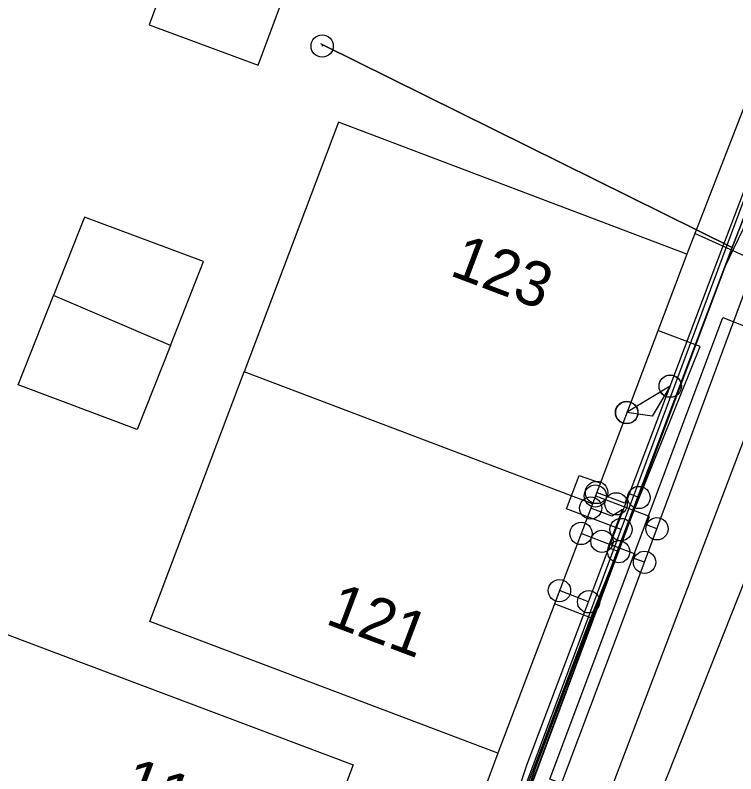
# Model space of a CAD drawing. Extents: x 192672 to 192910, y 446344 to 446512.
# Drawn here: x 192711.22 to 192727.4, y 446363.89 to 446380.91 of the extents above; entities that cross this region are included whole.
import ezdxf

# ---------------------------------------------------------------- set-up
doc = ezdxf.new("R2010")
doc.units = 0
for name, color, linetype in [('B-OI-KL-()_PUNTVANLEVERING_WATER-S', 7, 'Continuous'), ('B-OI-KL-BUISLEIDING_OLIEGASCHEMICALIEN_GASLAGEDRUK-G', 7, 'Continuous'), ('B-OI-KL-DATA-G', 7, 'Continuous'), ('B-OI-KL-DATA_GTWP-S', 7, 'Continuous'), ('B-OI-KL-DATA_HULPSTUK-S', 7, 'Continuous'), ('B-OI-KL-DATA_KABELBED-G', 7, 'Continuous'), ('B-OI-KL-DATA_MOF-S', 7, 'Continuous'), ('B-OI-KL-ET_LS-G', 7, 'Continuous'), ('B-OI-KL-ET_LS_DELIVERYPOINT-S', 7, 'Continuous'), ('B-OI-KL-ET_LS_MOF-S', 7, 'Continuous'), ('B-OI-KL-GAS_LD_AFTAKZADEL-S', 7, 'Continuous'), ('B-OI-KL-GAS_LD_DELIVERYPOINT-S', 7, 'Continuous'), ('B-OI-KL-GAS_LD_OVERGANGSSTUK-S', 7, 'Continuous'), ('B-OI-KL-WATER-G', 7, 'Continuous'), ('B-OI-RI-RIOOLVRIJVERVAL-G', 7, 'Continuous'), ('Default', 7, 'Continuous'), ('grens niveau plus 1', 7, 'Continuous'), ('huisnummerreeks BGT', 7, 'Continuous'), ('kant open verharding', 7, 'Continuous'), ('kant verharding', 7, 'Continuous'), ('pand op maaiveld vlak', 7, 'Continuous')]:
    doc.layers.add(name, color=color, linetype=linetype)

# ---------------------------------------------------------------- blocks, each defined once
blk = doc.blocks.new('B-OI-KL-DATA_HULPSTUK-S')
at = {"layer": 'Default'}
blk.add_circle((0, 0), 0.25, dxfattribs=at)
blk = doc.blocks.new('B-OI-KL-GAS_LD_AFTAKZADEL-S')
at = {"layer": 'Default'}
blk.add_circle((0, 0), 0.25, dxfattribs=at)
blk = doc.blocks.new('B-OI-KL-GAS_LD_DELIVERYPOINT-S')
at = {"layer": 'Default'}
blk.add_circle((0, 0), 0.25, dxfattribs=at)
blk = doc.blocks.new('B-OI-KL-GAS_LD_OVERGANGSSTUK-S')
at = {"layer": 'Default'}
blk.add_circle((0, 0), 0.25, dxfattribs=at)
blk = doc.blocks.new('B-OI-KL-ET_LS_DELIVERYPOINT-S')
at = {"layer": 'Default'}
blk.add_circle((0, 0), 0.25, dxfattribs=at)
blk = doc.blocks.new('B-OI-KL-ET_LS_MOF-S')
at = {"layer": 'Default'}
blk.add_circle((0, 0), 0.25, dxfattribs=at)
blk = doc.blocks.new('B-OI-KL-()_PUNTVANLEVERING_WATER-S')
at = {"layer": 'Default'}
blk.add_circle((0, 0), 0.25, dxfattribs=at)
blk = doc.blocks.new('B-OI-KL-DATA_GTWP-S')
at = {"layer": 'Default'}
blk.add_circle((0, 0), 0.25, dxfattribs=at)
blk = doc.blocks.new('B-OI-KL-DATA_MOF-S')
at = {"layer": 'Default'}
blk.add_circle((0, 0), 0.25, dxfattribs=at)

msp = doc.modelspace()

# ---------------------------------------------------------------- linework, layer by layer
at = {"layer": 'B-OI-KL-BUISLEIDING_OLIEGASCHEMICALIEN_GASLAGEDRUK-G'}
for points in [[(192716.663, 446345.556), (192724.878, 446367.369), (192730.944, 446383.739), (192732.424, 446387.662), (192733.825, 446391.479)], [(192724.71, 446369.947), (192724.242, 446370.124)], [(192725.626, 446369.387), (192725.391, 446369.473), (192725.461, 446369.662), (192724.71, 446369.947)], [(192724.391, 446369.105), (192723.923, 446369.282)], [(192725.348, 446368.636), (192725.113, 446368.723), (192725.148, 446368.818), (192724.391, 446369.105)]]:
    msp.add_lwpolyline(points, dxfattribs=at)
at = {"layer": 'B-OI-KL-DATA-G'}
for points in [[(192768.74, 446486.807), (192749.794, 446435.599), (192742.072, 446415.039), (192739.06, 446406.841), (192738.917, 446406.249), (192738.75, 446405.758), (192738.438, 446405.088), (192738.002, 446404.406), (192737.543, 446403.858), (192737.067, 446403.408), (192736.56, 446403.025), (192736.06, 446402.723), (192733.684, 446396.245), (192734.518, 446394.712), (192730.316, 446383.423), (192727.316, 446375.697), (192722.899, 446364.033), (192722.458, 446362.715), (192718.077, 446351.086), (192716.68, 446347.404), (192715.968, 446345.556)], [(192768.74, 446486.807), (192749.794, 446435.599), (192742.072, 446415.039), (192739.06, 446406.841), (192738.917, 446406.249), (192738.75, 446405.758), (192738.438, 446405.088), (192738.002, 446404.406), (192737.543, 446403.858), (192737.067, 446403.408), (192736.56, 446403.025), (192736.06, 446402.723), (192733.684, 446396.245), (192734.518, 446394.712), (192730.316, 446383.423), (192727.316, 446375.697), (192722.899, 446364.033), (192722.458, 446362.715), (192718.077, 446351.086), (192716.68, 446347.404), (192715.968, 446345.556)], [(192768.74, 446486.807), (192749.794, 446435.599), (192742.072, 446415.039), (192739.06, 446406.841), (192738.917, 446406.249), (192738.75, 446405.758), (192738.438, 446405.088), (192738.002, 446404.406), (192737.543, 446403.858), (192737.067, 446403.408), (192736.56, 446403.025), (192736.06, 446402.723), (192733.684, 446396.245), (192734.518, 446394.712), (192730.316, 446383.423), (192727.316, 446375.697), (192722.899, 446364.033), (192722.458, 446362.715), (192718.077, 446351.086), (192716.68, 446347.404), (192715.968, 446345.556)], [(192768.74, 446486.807), (192749.794, 446435.599), (192742.072, 446415.039), (192739.06, 446406.841), (192738.917, 446406.249), (192738.75, 446405.758), (192738.438, 446405.088), (192738.002, 446404.406), (192737.543, 446403.858), (192737.067, 446403.408), (192736.56, 446403.025), (192736.06, 446402.723), (192733.684, 446396.245), (192734.518, 446394.712), (192730.316, 446383.423), (192727.316, 446375.697), (192722.899, 446364.033), (192722.458, 446362.715), (192718.077, 446351.086), (192716.68, 446347.404), (192715.968, 446345.556)], [(192768.74, 446486.807), (192749.794, 446435.599), (192742.072, 446415.039), (192739.06, 446406.841), (192738.917, 446406.249), (192738.75, 446405.758), (192738.438, 446405.088), (192738.002, 446404.406), (192737.543, 446403.858), (192737.067, 446403.408), (192736.56, 446403.025), (192736.06, 446402.723), (192733.684, 446396.245), (192734.518, 446394.712), (192730.316, 446383.423), (192727.316, 446375.697), (192722.899, 446364.033), (192722.458, 446362.715), (192718.077, 446351.086), (192716.68, 446347.404), (192715.968, 446345.556)], [(192768.74, 446486.807), (192749.794, 446435.599), (192742.072, 446415.039), (192739.06, 446406.841), (192738.917, 446406.249), (192738.75, 446405.758), (192738.438, 446405.088), (192738.002, 446404.406), (192737.543, 446403.858), (192737.067, 446403.408), (192736.56, 446403.025), (192736.06, 446402.723), (192733.684, 446396.245), (192734.518, 446394.712), (192730.316, 446383.423), (192727.316, 446375.697), (192722.899, 446364.033), (192722.458, 446362.715), (192718.077, 446351.086), (192716.68, 446347.404), (192715.968, 446345.556)], [(192768.74, 446486.807), (192749.794, 446435.599), (192742.072, 446415.039), (192739.06, 446406.841), (192738.917, 446406.249), (192738.75, 446405.758), (192738.438, 446405.088), (192738.002, 446404.406), (192737.543, 446403.858), (192737.067, 446403.408), (192736.56, 446403.025), (192736.06, 446402.723), (192733.684, 446396.245), (192734.518, 446394.712), (192730.316, 446383.423), (192727.316, 446375.697), (192722.899, 446364.033), (192722.458, 446362.715), (192718.077, 446351.086), (192716.68, 446347.404), (192715.968, 446345.556)], [(192768.74, 446486.807), (192749.794, 446435.599), (192742.072, 446415.039), (192739.06, 446406.841), (192738.917, 446406.249), (192738.75, 446405.758), (192738.438, 446405.088), (192738.002, 446404.406), (192737.543, 446403.858), (192737.067, 446403.408), (192736.56, 446403.025), (192736.06, 446402.723), (192733.684, 446396.245), (192734.518, 446394.712), (192730.316, 446383.423), (192727.316, 446375.697), (192722.899, 446364.033), (192722.458, 446362.715), (192718.077, 446351.086), (192716.68, 446347.404), (192715.968, 446345.556)], [(192768.74, 446486.807), (192749.794, 446435.599), (192742.072, 446415.039), (192739.06, 446406.841), (192738.917, 446406.249), (192738.75, 446405.758), (192738.438, 446405.088), (192738.002, 446404.406), (192737.543, 446403.858), (192737.067, 446403.408), (192736.56, 446403.025), (192736.06, 446402.723), (192733.684, 446396.245), (192734.518, 446394.712), (192730.316, 446383.423), (192727.316, 446375.697), (192722.899, 446364.033), (192722.458, 446362.715), (192718.077, 446351.086), (192716.68, 446347.404), (192715.968, 446345.556)], [(192768.74, 446486.807), (192749.794, 446435.599), (192742.072, 446415.039), (192739.06, 446406.841), (192738.917, 446406.249), (192738.75, 446405.758), (192738.438, 446405.088), (192738.002, 446404.406), (192737.543, 446403.858), (192737.067, 446403.408), (192736.56, 446403.025), (192736.06, 446402.723), (192733.684, 446396.245), (192734.518, 446394.712), (192730.316, 446383.423), (192727.316, 446375.697), (192722.899, 446364.033), (192722.458, 446362.715), (192718.077, 446351.086), (192716.68, 446347.404), (192715.968, 446345.556)], [(192768.74, 446486.807), (192749.794, 446435.599), (192742.072, 446415.039), (192739.06, 446406.841), (192738.917, 446406.249), (192738.75, 446405.758), (192738.438, 446405.088), (192738.002, 446404.406), (192737.543, 446403.858), (192737.067, 446403.408), (192736.56, 446403.025), (192736.06, 446402.723), (192733.684, 446396.245), (192734.518, 446394.712), (192730.316, 446383.423), (192727.316, 446375.697), (192722.899, 446364.033), (192722.458, 446362.715), (192718.077, 446351.086), (192716.68, 446347.404), (192715.968, 446345.556)], [(192768.74, 446486.807), (192749.794, 446435.599), (192742.072, 446415.039), (192739.06, 446406.841), (192738.917, 446406.249), (192738.75, 446405.758), (192738.438, 446405.088), (192738.002, 446404.406), (192737.543, 446403.858), (192737.067, 446403.408), (192736.56, 446403.025), (192736.06, 446402.723), (192733.684, 446396.245), (192734.518, 446394.712), (192730.316, 446383.423), (192727.316, 446375.697), (192722.899, 446364.033), (192722.458, 446362.715), (192718.077, 446351.086), (192716.68, 446347.404), (192715.968, 446345.556)], [(192768.74, 446486.807), (192749.794, 446435.599), (192742.072, 446415.039), (192739.06, 446406.841), (192738.917, 446406.249), (192738.75, 446405.758), (192738.438, 446405.088), (192738.002, 446404.406), (192737.543, 446403.858), (192737.067, 446403.408), (192736.56, 446403.025), (192736.06, 446402.723), (192733.684, 446396.245), (192734.518, 446394.712), (192730.316, 446383.423), (192727.316, 446375.697), (192722.899, 446364.033), (192722.458, 446362.715), (192718.077, 446351.086), (192716.68, 446347.404), (192715.968, 446345.556)], [(192768.74, 446486.807), (192749.794, 446435.599), (192742.072, 446415.039), (192739.06, 446406.841), (192738.917, 446406.249), (192738.75, 446405.758), (192738.438, 446405.088), (192738.002, 446404.406), (192737.543, 446403.858), (192737.067, 446403.408), (192736.56, 446403.025), (192736.06, 446402.723), (192733.684, 446396.245), (192734.518, 446394.712), (192730.316, 446383.423), (192727.316, 446375.697), (192722.899, 446364.033), (192722.458, 446362.715), (192718.077, 446351.086), (192716.68, 446347.404), (192715.968, 446345.556)], [(192768.74, 446486.807), (192749.794, 446435.599), (192742.072, 446415.039), (192739.06, 446406.841), (192738.917, 446406.249), (192738.75, 446405.758), (192738.438, 446405.088), (192738.002, 446404.406), (192737.543, 446403.858), (192737.067, 446403.408), (192736.56, 446403.025), (192736.06, 446402.723), (192733.684, 446396.245), (192734.518, 446394.712), (192730.316, 446383.423), (192727.316, 446375.697), (192722.899, 446364.033), (192722.458, 446362.715), (192718.077, 446351.086), (192716.68, 446347.404), (192715.968, 446345.556)], [(192675.743, 446430.156), (192678.122, 446429.261), (192683.193, 446427.673), (192696.077, 446422.823), (192719.012, 446414.118), (192720.2, 446413.77), (192739.06, 446406.841), (192738.917, 446406.249), (192738.75, 446405.758), (192738.438, 446405.088), (192738.002, 446404.406), (192737.543, 446403.858), (192737.067, 446403.408), (192736.56, 446403.025), (192736.06, 446402.723), (192733.684, 446396.245), (192734.518, 446394.712), (192730.316, 446383.423), (192727.316, 446375.697), (192722.899, 446364.033), (192722.458, 446362.715), (192718.077, 446351.086), (192716.68, 446347.404), (192715.968, 446345.556)], [(192675.743, 446430.156), (192678.122, 446429.261), (192683.193, 446427.673), (192696.077, 446422.823), (192719.012, 446414.118), (192720.2, 446413.77), (192739.06, 446406.841), (192738.917, 446406.249), (192738.75, 446405.758), (192738.438, 446405.088), (192738.002, 446404.406), (192737.543, 446403.858), (192737.067, 446403.408), (192736.56, 446403.025), (192736.06, 446402.723), (192733.684, 446396.245), (192734.518, 446394.712), (192730.316, 446383.423), (192727.316, 446375.697), (192722.899, 446364.033), (192722.458, 446362.715), (192718.077, 446351.086), (192716.68, 446347.404), (192715.968, 446345.556)], [(192675.743, 446430.156), (192678.122, 446429.261), (192683.193, 446427.673), (192696.077, 446422.823), (192719.012, 446414.118), (192720.2, 446413.77), (192739.06, 446406.841), (192738.917, 446406.249), (192738.75, 446405.758), (192738.438, 446405.088), (192738.002, 446404.406), (192737.543, 446403.858), (192737.067, 446403.408), (192736.56, 446403.025), (192736.06, 446402.723), (192733.684, 446396.245), (192734.518, 446394.712), (192730.316, 446383.423), (192727.316, 446375.697), (192722.899, 446364.033), (192722.458, 446362.715), (192718.077, 446351.086), (192716.68, 446347.404), (192715.968, 446345.556)], [(192675.743, 446430.156), (192678.122, 446429.261), (192683.193, 446427.673), (192696.077, 446422.823), (192719.012, 446414.118), (192720.2, 446413.77), (192739.06, 446406.841), (192738.917, 446406.249), (192738.75, 446405.758), (192738.438, 446405.088), (192738.002, 446404.406), (192737.543, 446403.858), (192737.067, 446403.408), (192736.56, 446403.025), (192736.06, 446402.723), (192733.684, 446396.245), (192734.518, 446394.712), (192730.316, 446383.423), (192727.316, 446375.697), (192722.899, 446364.033), (192722.458, 446362.715), (192718.077, 446351.086), (192716.68, 446347.404), (192715.968, 446345.556)], [(192675.743, 446430.156), (192678.122, 446429.261), (192683.193, 446427.673), (192696.077, 446422.823), (192719.012, 446414.118), (192720.2, 446413.77), (192739.06, 446406.841), (192738.917, 446406.249), (192738.75, 446405.758), (192738.438, 446405.088), (192738.002, 446404.406), (192737.543, 446403.858), (192737.067, 446403.408), (192736.56, 446403.025), (192736.06, 446402.723), (192733.684, 446396.245), (192734.518, 446394.712), (192730.316, 446383.423), (192727.316, 446375.697), (192722.899, 446364.033), (192722.458, 446362.715), (192718.077, 446351.086), (192716.68, 446347.404), (192715.968, 446345.556)], [(192675.743, 446430.156), (192678.122, 446429.261), (192683.193, 446427.673), (192696.077, 446422.823), (192719.012, 446414.118), (192720.2, 446413.77), (192739.06, 446406.841), (192738.917, 446406.249), (192738.75, 446405.758), (192738.438, 446405.088), (192738.002, 446404.406), (192737.543, 446403.858), (192737.067, 446403.408), (192736.56, 446403.025), (192736.06, 446402.723), (192733.684, 446396.245), (192734.518, 446394.712), (192730.316, 446383.423), (192727.316, 446375.697), (192722.899, 446364.033), (192722.458, 446362.715), (192718.077, 446351.086), (192716.68, 446347.404), (192715.968, 446345.556)], [(192715.968, 446345.556), (192716.68, 446347.404), (192718.077, 446351.086), (192722.458, 446362.715), (192722.899, 446364.033), (192727.316, 446375.697), (192730.316, 446383.423), (192734.518, 446394.712), (192733.684, 446396.245), (192736.06, 446402.723), (192736.56, 446403.025), (192737.067, 446403.408), (192737.543, 446403.858), (192738.002, 446404.406), (192738.438, 446405.088), (192738.75, 446405.758), (192738.917, 446406.249), (192739.06, 446406.841), (192720.2, 446413.77), (192719.012, 446414.118), (192698.154, 446422.035)], [(192715.968, 446345.556), (192716.68, 446347.404), (192718.077, 446351.086), (192722.458, 446362.715), (192722.899, 446364.033), (192727.316, 446375.697), (192730.316, 446383.423), (192734.518, 446394.712), (192733.684, 446396.245), (192736.06, 446402.723), (192736.56, 446403.025), (192737.067, 446403.408), (192737.543, 446403.858), (192738.002, 446404.406), (192738.438, 446405.088), (192738.75, 446405.758), (192738.917, 446406.249), (192739.06, 446406.841), (192720.2, 446413.77), (192719.012, 446414.118), (192703.056, 446420.174)], [(192715.968, 446345.556), (192716.68, 446347.404), (192718.077, 446351.086), (192722.458, 446362.715), (192722.899, 446364.033), (192727.316, 446375.697), (192730.316, 446383.423), (192734.518, 446394.712), (192733.684, 446396.245), (192736.06, 446402.723), (192736.56, 446403.025), (192737.067, 446403.408), (192737.543, 446403.858), (192738.002, 446404.406), (192738.438, 446405.088), (192738.75, 446405.758), (192738.917, 446406.249), (192739.06, 446406.841), (192720.2, 446413.77), (192719.012, 446414.118), (192707.704, 446418.41)], [(192733.785, 446392.743), (192730.316, 446383.423), (192727.316, 446375.697), (192722.899, 446364.033), (192722.458, 446362.715), (192718.077, 446351.086), (192716.68, 446347.404), (192715.968, 446345.556)], [(192718.113, 446380.217), (192718.126, 446380.244), (192727.316, 446375.697), (192730.316, 446383.423), (192731.53, 446386.684), (192730.686, 446386.998)], [(192718.113, 446380.217), (192718.126, 446380.244), (192727.316, 446375.697), (192722.899, 446364.033), (192722.458, 446362.715), (192718.077, 446351.086), (192716.68, 446347.404), (192715.968, 446345.556)], [(192718.113, 446380.217), (192718.126, 446380.244), (192727.316, 446375.697), (192722.899, 446364.033), (192722.458, 446362.715), (192718.077, 446351.086), (192716.68, 446347.404), (192715.968, 446345.556)], [(192718.113, 446380.217), (192718.126, 446380.244), (192727.316, 446375.697), (192722.899, 446364.033), (192722.458, 446362.715), (192718.077, 446351.086), (192716.68, 446347.404), (192715.968, 446345.556)], [(192718.113, 446380.217), (192718.126, 446380.244), (192727.316, 446375.697), (192722.899, 446364.033), (192722.458, 446362.715), (192718.077, 446351.086), (192716.68, 446347.404), (192715.968, 446345.556)], [(192718.113, 446380.217), (192718.126, 446380.244), (192727.316, 446375.697), (192722.899, 446364.033), (192722.458, 446362.715), (192718.077, 446351.086), (192716.68, 446347.404), (192715.968, 446345.556)], [(192718.113, 446380.217), (192718.126, 446380.244), (192727.316, 446375.697), (192722.899, 446364.033), (192722.458, 446362.715), (192718.077, 446351.086), (192716.68, 446347.404), (192715.968, 446345.556)], [(192718.113, 446380.217), (192718.126, 446380.244), (192727.316, 446375.697), (192722.899, 446364.033), (192722.458, 446362.715), (192718.077, 446351.086), (192716.68, 446347.404), (192715.968, 446345.556)], [(192718.113, 446380.217), (192718.126, 446380.244), (192727.316, 446375.697), (192722.899, 446364.033), (192722.458, 446362.715), (192718.077, 446351.086), (192716.68, 446347.404), (192716.398, 446346.672)], [(192718.113, 446380.217), (192718.126, 446380.244), (192727.316, 446375.697), (192722.899, 446364.033), (192722.458, 446362.715), (192718.202, 446351.418)], [(192718.113, 446380.217), (192718.126, 446380.244), (192727.316, 446375.697), (192722.899, 446364.033), (192722.458, 446362.715), (192720.004, 446356.201)], [(192718.113, 446380.217), (192718.126, 446380.244), (192727.316, 446375.697), (192722.899, 446364.033), (192722.458, 446362.715), (192720.004, 446356.201)], [(192718.113, 446380.217), (192718.126, 446380.244), (192727.316, 446375.697), (192722.899, 446364.033), (192722.458, 446362.715), (192721.736, 446360.798)], [(192724.145, 446367.389), (192726.598, 446373.478), (192725.648, 446373.838)], [(192724.145, 446367.389), (192723.324, 446367.7)], [(192721.22, 446359.661), (192724.145, 446367.389)]]:
    msp.add_lwpolyline(points, dxfattribs=at)
at = {"layer": 'B-OI-KL-DATA_KABELBED-G'}
for points in [[(192715.778, 446345.556), (192717.157, 446349.216), (192720.197, 446357.284), (192722.27, 446362.784), (192722.711, 446364.103), (192724.092, 446367.75), (192725.922, 446372.585), (192725.924, 446372.588), (192726.95, 446375.299), (192730.073, 446383.511), (192734.61, 446395.441)], [(192731.53, 446386.684), (192727.316, 446375.697)], [(192718.126, 446380.244), (192718.08, 446380.267)], [(192718.113, 446380.217), (192718.126, 446380.244)], [(192727.316, 446375.697), (192718.126, 446380.244)], [(192727.316, 446375.697), (192721.736, 446360.798)], [(192725.922, 446372.585), (192725.921, 446372.584), (192724.944, 446371.997)], [(192725.924, 446372.588), (192725.921, 446372.584), (192725.515, 446371.91), (192724.95, 446371.994)], [(192724.092, 446367.75), (192723.438, 446368)]]:
    msp.add_lwpolyline(points, dxfattribs=at)
at = {"layer": 'B-OI-KL-ET_LS-G'}
for points in [[(192716.073, 446345.556), (192727.138, 446375.229), (192730.971, 446383.179), (192732.504, 446387.295), (192732.765, 446387.575)], [(192725.221, 446370.089), (192724.987, 446370.176), (192724.906, 446369.96), (192724.271, 446370.201)], [(192724.767, 446368.872), (192724.535, 446368.966), (192724.854, 446369.819), (192724.615, 446369.667), (192724.139, 446369.852)]]:
    msp.add_lwpolyline(points, dxfattribs=at)
at = {"layer": 'B-OI-KL-WATER-G'}
for points in [[(192715.942, 446345.556), (192716.677, 446347.527), (192733.49, 446392.627), (192735.123, 446396.62)], [(192724.065, 446369.656), (192723.597, 446369.833), (192723.883, 446370.586), (192724.353, 446370.417)], [(192724.82, 446369.37), (192724.065, 446369.656)]]:
    msp.add_lwpolyline(points, dxfattribs=at)
at = {"layer": 'B-OI-RI-RIOOLVRIJVERVAL-G'}
msp.add_line((192718.603, 446345.556), (192727.764, 446368.64), dxfattribs=at)
msp.add_lwpolyline([(192726.472, 446376.016), (192731.741, 446373.632)], dxfattribs=at)
at = {"layer": 'grens niveau plus 1'}
msp.add_lwpolyline([(192717.516, 446382.047), (192715.072, 446382.958), (192714.229, 446380.696), (192716.674, 446379.786), (192717.516, 446382.047)], dxfattribs=at)
at = {"layer": 'kant open verharding'}
for p, q in [((192729.467, 446383.724), (192726.296, 446375.548)), ((192722.057, 446364.352), (192715.03, 446345.556))]:
    msp.add_line(p, q, dxfattribs=at)
at = {"layer": 'kant verharding'}
msp.add_line((192724.36, 446362.912), (192728.589, 446374.052), dxfattribs=at)
msp.add_lwpolyline([(192724.074, 446363.455), (192723.221, 446363.769), (192727.106, 446374.125), (192727.941, 446373.798)], dxfattribs=at)
at = {"layer": 'pand op maaiveld vlak'}
for p, q in [((192726.296, 446375.548), (192724.176, 446369.95)), ((192714.709, 446373.499), (192712.083, 446374.618)), ((192724.176, 446369.95), (192716.363, 446372.909)), ((192724.176, 446369.95), (192722.057, 446364.352))]:
    msp.add_line(p, q, dxfattribs=at)
for points in [[(192726.296, 446375.548), (192718.482, 446378.507), (192716.363, 446372.909)], [(192714.709, 446373.499), (192715.452, 446375.385), (192712.777, 446376.376), (192712.083, 446374.618)], [(192714.709, 446373.499), (192713.965, 446371.612), (192711.293, 446372.613), (192712.083, 446374.618)], [(192722.057, 446364.352), (192714.243, 446367.31), (192716.363, 446372.909)], [(192705.936, 446363.845), (192707.619, 446368.308), (192711.656, 446366.786), (192718.809, 446364.09), (192717.127, 446359.628)]]:
    msp.add_lwpolyline(points, dxfattribs=at)

# ---------------------------------------------------------------- block references
at = {"layer": 'B-OI-KL-()_PUNTVANLEVERING_WATER-S'}
msp.add_blockref('B-OI-KL-()_PUNTVANLEVERING_WATER-S', (192724.82, 446369.37), dxfattribs=at)
at = {"layer": 'B-OI-KL-DATA_GTWP-S'}
for p in [(192725.922, 446372.585), (192725.924, 446372.588), (192724.944, 446371.997), (192724.95, 446371.994), (192723.438, 446368), (192724.092, 446367.75)]:
    msp.add_blockref('B-OI-KL-DATA_GTWP-S', p, dxfattribs=at)
at = {"layer": 'B-OI-KL-DATA_HULPSTUK-S'}
msp.add_blockref('B-OI-KL-DATA_HULPSTUK-S', (192718.113, 446380.217), dxfattribs=at)
at = {"layer": 'B-OI-KL-DATA_MOF-S'}
for p in [(192725.922, 446372.585), (192725.924, 446372.588), (192724.092, 446367.75)]:
    msp.add_blockref('B-OI-KL-DATA_MOF-S', p, dxfattribs=at)
at = {"layer": 'B-OI-KL-ET_LS_DELIVERYPOINT-S'}
for p in [(192724.271, 446370.201), (192724.139, 446369.852)]:
    msp.add_blockref('B-OI-KL-ET_LS_DELIVERYPOINT-S', p, dxfattribs=at)
at = {"layer": 'B-OI-KL-ET_LS_MOF-S'}
for p in [(192725.221, 446370.089), (192724.767, 446368.872)]:
    msp.add_blockref('B-OI-KL-ET_LS_MOF-S', p, dxfattribs=at)
at = {"layer": 'B-OI-KL-GAS_LD_AFTAKZADEL-S'}
for p in [(192725.626, 446369.387), (192725.348, 446368.636)]:
    msp.add_blockref('B-OI-KL-GAS_LD_AFTAKZADEL-S', p, dxfattribs=at)
at = {"layer": 'B-OI-KL-GAS_LD_DELIVERYPOINT-S'}
for p in [(192724.242, 446370.124), (192723.923, 446369.282)]:
    msp.add_blockref('B-OI-KL-GAS_LD_DELIVERYPOINT-S', p, dxfattribs=at)
at = {"layer": 'B-OI-KL-GAS_LD_OVERGANGSSTUK-S'}
for p in [(192724.71, 446369.947), (192724.391, 446369.105)]:
    msp.add_blockref('B-OI-KL-GAS_LD_OVERGANGSSTUK-S', p, dxfattribs=at)

# ---------------------------------------------------------------- texts
at = {"layer": 'huisnummerreeks BGT'}
for s, rotation, p in [('123', 339.3, (192720.947, 446375.084)), ('121', 339.3, (192718.161, 446367.266)), ('119', 339.4, (192713.551, 446363.347))]:
    msp.add_text(s, height=1, rotation=rotation, dxfattribs=at).set_placement(p)

doc.saveas('drawing.dxf')
